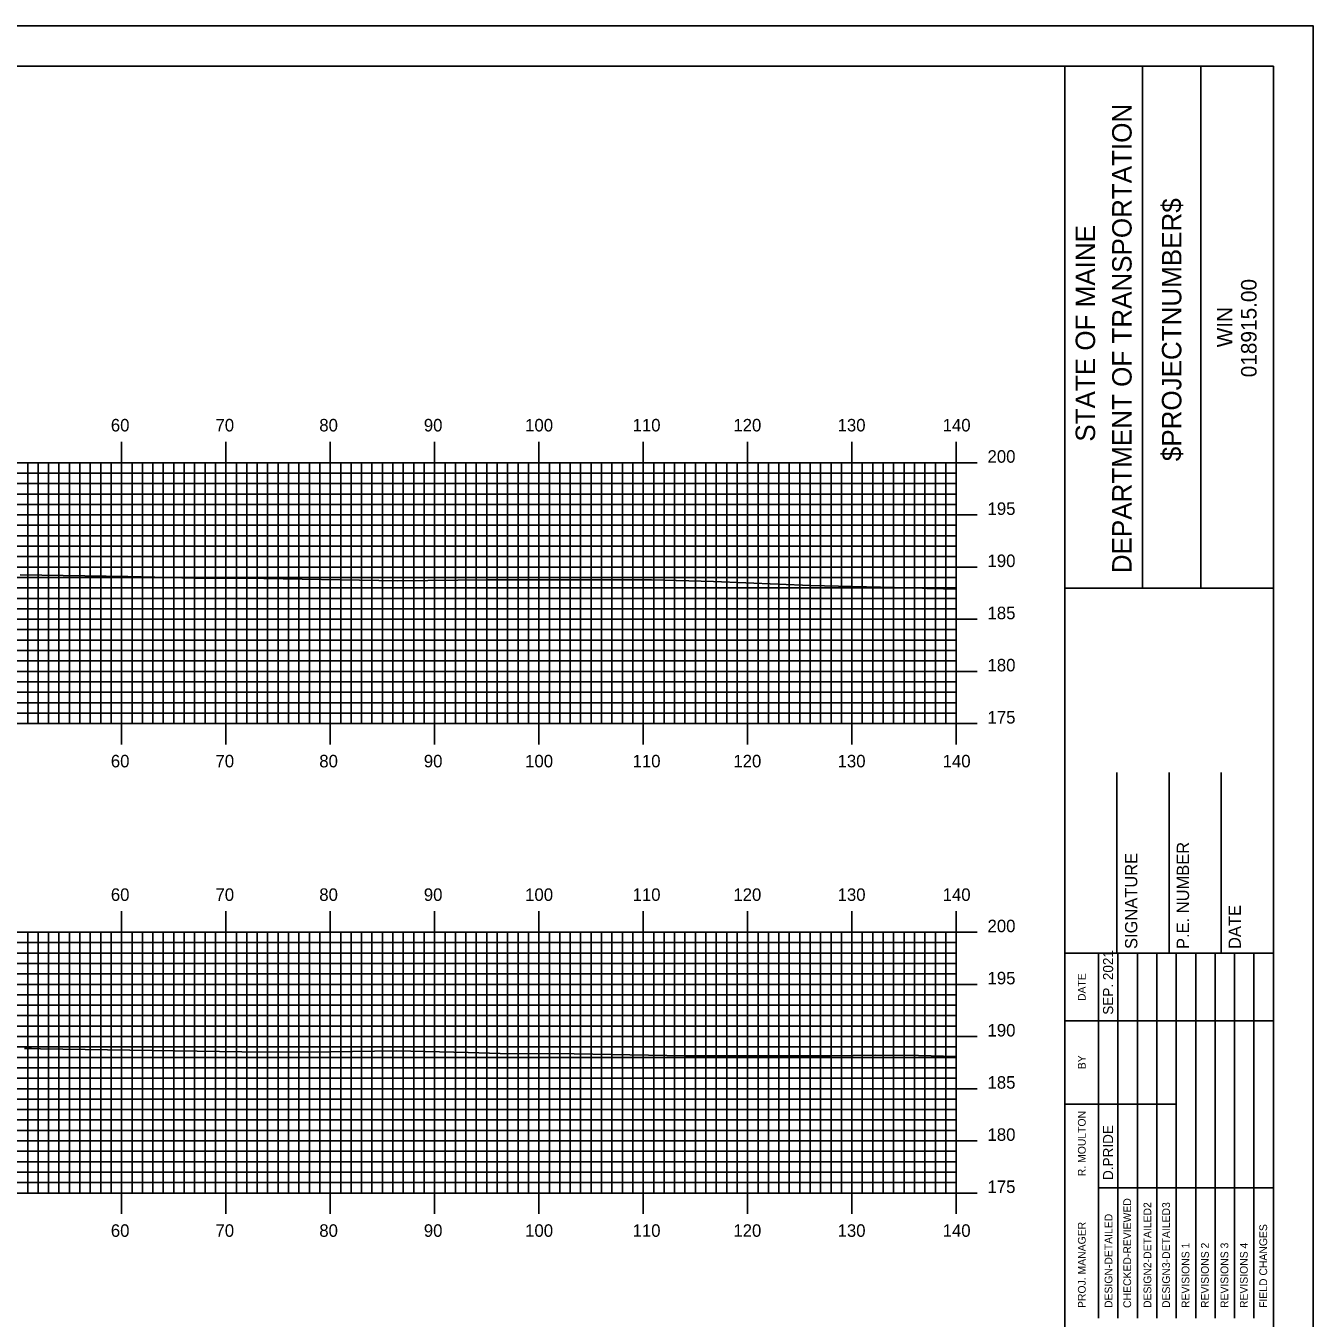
# Model space of a CAD drawing. Extents: x 1797994 to 1798337, y 442591 to 442811.
# Drawn here: x 1798210.8 to 1798334.2, y 442686.7 to 442810.5 of the extents above; entities that cross this region are included whole.
import ezdxf

# ---------------------------------------------------------------- set-up
doc = ezdxf.new("R2010")
doc.units = 0
for name, color, linetype in [('BORDER', 7, 'Continuous'), ('H_V ANNOTATION', 7, 'Continuous'), ('MAJOR', 7, 'Continuous'), ('MINOR', 7, 'Continuous'), ('PLOT BOUNDARY', 7, 'Continuous'), ('S_Roadway_Centerline', 7, 'Continuous')]:
    doc.layers.add(name, color=color, linetype=linetype)

msp = doc.modelspace()

# ---------------------------------------------------------------- linework, layer by layer
at = {"layer": 'BORDER'}
for p, q in [((1798310.36, 442596.67), (1798310.36, 442806.67)), ((1798317.81, 442756.66), (1798317.81, 442806.66)), ((1798323.4, 442756.66), (1798323.4, 442806.66)), ((1798310.36, 442756.65), (1798330.36, 442756.65)), ((1798315.36, 442721.67), (1798315.36, 442738.97)), ((1798320.36, 442721.67), (1798320.36, 442738.97)), ((1798325.36, 442721.67), (1798325.36, 442738.97)), ((1798310.36, 442721.67), (1798330.36, 442721.67))]:
    msp.add_line(p, q, dxfattribs=at)
msp.add_lwpolyline([(1798010.36, 442596.67), (1798330.36, 442596.67), (1798330.36, 442806.67), (1798010.36, 442806.67)], close=True, dxfattribs=at)
for points in [[(1798313.59, 442715.17), (1798313.59, 442721.67)], [(1798315.45, 442686.68), (1798315.45, 442721.67)], [(1798317.32, 442721.67), (1798317.32, 442686.68)], [(1798319.18, 442686.68), (1798319.18, 442721.67)], [(1798321.04, 442686.68), (1798321.04, 442721.67)], [(1798322.91, 442686.68), (1798322.91, 442721.67)], [(1798324.77, 442686.68), (1798324.77, 442721.67)], [(1798326.63, 442686.68), (1798326.63, 442721.67)], [(1798328.5, 442686.68), (1798328.5, 442721.67)], [(1798313.59, 442686.68), (1798313.59, 442720.26)], [(1798310.36, 442715.17), (1798330.36, 442715.17)], [(1798310.36, 442707.17), (1798313.59, 442707.17)], [(1798313.59, 442707.17), (1798321.04, 442707.17)], [(1798313.59, 442699.17), (1798330.36, 442699.17)]]:
    msp.add_lwpolyline(points, dxfattribs=at)
at = {"layer": 'MAJOR'}
for p, q in [((1798219.96, 442770.67), (1798219.96, 442768.67)), ((1798229.96, 442770.67), (1798229.96, 442768.67)), ((1798239.96, 442770.67), (1798239.96, 442768.67)), ((1798249.96, 442770.67), (1798249.96, 442768.67)), ((1798259.96, 442770.67), (1798259.96, 442768.67)), ((1798269.96, 442770.67), (1798269.96, 442768.67)), ((1798279.96, 442770.67), (1798279.96, 442768.67)), ((1798289.96, 442770.67), (1798289.96, 442768.67)), ((1798299.96, 442770.67), (1798299.96, 442768.67)), ((1798019.96, 442768.67), (1798299.96, 442768.67)), ((1798019.96, 442768.67), (1798299.96, 442768.67)), ((1798219.96, 442743.67), (1798219.96, 442768.67)), ((1798229.96, 442743.67), (1798229.96, 442768.67)), ((1798239.96, 442743.67), (1798239.96, 442768.67)), ((1798249.96, 442743.67), (1798249.96, 442768.67)), ((1798259.96, 442743.67), (1798259.96, 442768.67)), ((1798269.96, 442743.67), (1798269.96, 442768.67)), ((1798279.96, 442743.67), (1798279.96, 442768.67)), ((1798289.96, 442743.67), (1798289.96, 442768.67)), ((1798301.96, 442768.67), (1798297.95, 442768.67)), ((1798299.96, 442743.67), (1798299.96, 442768.67)), ((1798299.96, 442743.67), (1798299.96, 442768.67)), ((1798019.96, 442763.67), (1798299.96, 442763.67)), ((1798301.96, 442763.67), (1798297.95, 442763.67)), ((1798019.96, 442758.67), (1798299.96, 442758.67)), ((1798301.96, 442758.67), (1798297.95, 442758.67)), ((1798019.96, 442753.67), (1798299.96, 442753.67)), ((1798301.96, 442753.67), (1798297.95, 442753.67)), ((1798019.96, 442748.67), (1798299.96, 442748.67)), ((1798301.96, 442748.67), (1798297.95, 442748.67)), ((1798019.96, 442743.67), (1798299.96, 442743.67)), ((1798019.96, 442743.67), (1798299.96, 442743.67)), ((1798219.96, 442741.66), (1798219.96, 442743.67)), ((1798229.96, 442741.66), (1798229.96, 442743.67)), ((1798239.96, 442741.66), (1798239.96, 442743.67)), ((1798249.96, 442741.66), (1798249.96, 442743.67)), ((1798259.96, 442741.66), (1798259.96, 442743.67)), ((1798269.96, 442741.66), (1798269.96, 442743.67)), ((1798279.96, 442741.66), (1798279.96, 442743.67)), ((1798289.96, 442741.66), (1798289.96, 442743.67)), ((1798301.96, 442743.67), (1798297.95, 442743.67)), ((1798299.96, 442741.66), (1798299.96, 442743.67)), ((1798219.96, 442725.67), (1798219.96, 442723.67)), ((1798229.96, 442725.67), (1798229.96, 442723.67)), ((1798239.96, 442725.67), (1798239.96, 442723.67)), ((1798249.96, 442725.67), (1798249.96, 442723.67)), ((1798259.96, 442725.67), (1798259.96, 442723.67)), ((1798269.96, 442725.67), (1798269.96, 442723.67)), ((1798279.96, 442725.67), (1798279.96, 442723.67)), ((1798289.96, 442725.67), (1798289.96, 442723.67)), ((1798299.96, 442725.67), (1798299.96, 442723.67)), ((1798019.96, 442723.67), (1798299.96, 442723.67)), ((1798019.96, 442723.67), (1798299.96, 442723.67)), ((1798219.96, 442698.67), (1798219.96, 442723.67)), ((1798229.96, 442698.67), (1798229.96, 442723.67)), ((1798239.96, 442698.67), (1798239.96, 442723.67)), ((1798249.96, 442698.67), (1798249.96, 442723.67)), ((1798259.96, 442698.67), (1798259.96, 442723.67)), ((1798269.96, 442698.67), (1798269.96, 442723.67)), ((1798279.96, 442698.67), (1798279.96, 442723.67)), ((1798289.96, 442698.67), (1798289.96, 442723.67)), ((1798301.96, 442723.67), (1798297.95, 442723.67)), ((1798299.96, 442698.67), (1798299.96, 442723.67)), ((1798299.96, 442698.67), (1798299.96, 442723.67)), ((1798019.96, 442718.67), (1798299.96, 442718.67)), ((1798301.96, 442718.67), (1798297.95, 442718.67)), ((1798019.96, 442713.67), (1798299.96, 442713.67)), ((1798301.96, 442713.67), (1798297.95, 442713.67)), ((1798019.96, 442708.67), (1798299.96, 442708.67)), ((1798301.96, 442708.67), (1798297.95, 442708.67)), ((1798019.96, 442703.67), (1798299.96, 442703.67)), ((1798301.96, 442703.67), (1798297.95, 442703.67)), ((1798019.96, 442698.67), (1798299.96, 442698.67)), ((1798019.96, 442698.67), (1798299.96, 442698.67)), ((1798219.96, 442696.66), (1798219.96, 442698.67)), ((1798229.96, 442696.66), (1798229.96, 442698.67)), ((1798239.96, 442696.66), (1798239.96, 442698.67)), ((1798249.96, 442696.66), (1798249.96, 442698.67)), ((1798259.96, 442696.66), (1798259.96, 442698.67)), ((1798269.96, 442696.66), (1798269.96, 442698.67)), ((1798279.96, 442696.66), (1798279.96, 442698.67)), ((1798289.96, 442696.66), (1798289.96, 442698.67)), ((1798301.96, 442698.67), (1798297.95, 442698.67)), ((1798299.96, 442696.66), (1798299.96, 442698.67))]:
    msp.add_line(p, q, dxfattribs=at)
at = {"layer": 'MINOR'}
for p, q in [((1798210.96, 442743.67), (1798210.96, 442768.67)), ((1798211.96, 442743.67), (1798211.96, 442768.67)), ((1798212.96, 442743.67), (1798212.96, 442768.67)), ((1798213.96, 442743.67), (1798213.96, 442768.67)), ((1798214.96, 442743.67), (1798214.96, 442768.67)), ((1798215.96, 442743.67), (1798215.96, 442768.67)), ((1798216.96, 442743.67), (1798216.96, 442768.67)), ((1798217.96, 442743.67), (1798217.96, 442768.67)), ((1798218.96, 442743.67), (1798218.96, 442768.67)), ((1798220.96, 442743.67), (1798220.96, 442768.67)), ((1798221.96, 442743.67), (1798221.96, 442768.67)), ((1798222.96, 442743.67), (1798222.96, 442768.67)), ((1798223.96, 442743.67), (1798223.96, 442768.67)), ((1798224.96, 442743.67), (1798224.96, 442768.67)), ((1798225.96, 442743.67), (1798225.96, 442768.67)), ((1798226.96, 442743.67), (1798226.96, 442768.67)), ((1798227.96, 442743.67), (1798227.96, 442768.67)), ((1798228.96, 442743.67), (1798228.96, 442768.67)), ((1798230.96, 442743.67), (1798230.96, 442768.67)), ((1798231.96, 442743.67), (1798231.96, 442768.67)), ((1798232.96, 442743.67), (1798232.96, 442768.67)), ((1798233.96, 442743.67), (1798233.96, 442768.67)), ((1798234.96, 442743.67), (1798234.96, 442768.67)), ((1798235.96, 442743.67), (1798235.96, 442768.67)), ((1798236.96, 442743.67), (1798236.96, 442768.67)), ((1798237.96, 442743.67), (1798237.96, 442768.67)), ((1798238.96, 442743.67), (1798238.96, 442768.67)), ((1798240.96, 442743.67), (1798240.96, 442768.67)), ((1798241.96, 442743.67), (1798241.96, 442768.67)), ((1798242.96, 442743.67), (1798242.96, 442768.67)), ((1798243.96, 442743.67), (1798243.96, 442768.67)), ((1798244.96, 442743.67), (1798244.96, 442768.67)), ((1798245.96, 442743.67), (1798245.96, 442768.67)), ((1798246.96, 442743.67), (1798246.96, 442768.67)), ((1798247.96, 442743.67), (1798247.96, 442768.67)), ((1798248.96, 442743.67), (1798248.96, 442768.67)), ((1798250.96, 442743.67), (1798250.96, 442768.67)), ((1798251.96, 442743.67), (1798251.96, 442768.67)), ((1798252.96, 442743.67), (1798252.96, 442768.67)), ((1798253.96, 442743.67), (1798253.96, 442768.67)), ((1798254.96, 442743.67), (1798254.96, 442768.67)), ((1798255.96, 442743.67), (1798255.96, 442768.67)), ((1798256.96, 442743.67), (1798256.96, 442768.67)), ((1798257.96, 442743.67), (1798257.96, 442768.67)), ((1798258.96, 442743.67), (1798258.96, 442768.67)), ((1798260.96, 442743.67), (1798260.96, 442768.67)), ((1798261.96, 442743.67), (1798261.96, 442768.67)), ((1798262.96, 442743.67), (1798262.96, 442768.67)), ((1798263.96, 442743.67), (1798263.96, 442768.67)), ((1798264.96, 442743.67), (1798264.96, 442768.67)), ((1798265.96, 442743.67), (1798265.96, 442768.67)), ((1798266.96, 442743.67), (1798266.96, 442768.67)), ((1798267.96, 442743.67), (1798267.96, 442768.67)), ((1798268.96, 442743.67), (1798268.96, 442768.67)), ((1798270.96, 442743.67), (1798270.96, 442768.67)), ((1798271.96, 442743.67), (1798271.96, 442768.67)), ((1798272.96, 442743.67), (1798272.96, 442768.67)), ((1798273.96, 442743.67), (1798273.96, 442768.67)), ((1798274.96, 442743.67), (1798274.96, 442768.67)), ((1798275.96, 442743.67), (1798275.96, 442768.67)), ((1798276.96, 442743.67), (1798276.96, 442768.67)), ((1798277.96, 442743.67), (1798277.96, 442768.67)), ((1798278.96, 442743.67), (1798278.96, 442768.67)), ((1798280.96, 442743.67), (1798280.96, 442768.67)), ((1798281.96, 442743.67), (1798281.96, 442768.67)), ((1798282.96, 442743.67), (1798282.96, 442768.67)), ((1798283.96, 442743.67), (1798283.96, 442768.67)), ((1798284.96, 442743.67), (1798284.96, 442768.67)), ((1798285.96, 442743.67), (1798285.96, 442768.67)), ((1798286.96, 442743.67), (1798286.96, 442768.67)), ((1798287.96, 442743.67), (1798287.96, 442768.67)), ((1798288.96, 442743.67), (1798288.96, 442768.67)), ((1798290.96, 442743.67), (1798290.96, 442768.67)), ((1798291.96, 442743.67), (1798291.96, 442768.67)), ((1798292.96, 442743.67), (1798292.96, 442768.67)), ((1798293.96, 442743.67), (1798293.96, 442768.67)), ((1798294.96, 442743.67), (1798294.96, 442768.67)), ((1798295.96, 442743.67), (1798295.96, 442768.67)), ((1798296.96, 442743.67), (1798296.96, 442768.67)), ((1798297.96, 442743.67), (1798297.96, 442768.67)), ((1798298.96, 442743.67), (1798298.96, 442768.67)), ((1798019.96, 442767.67), (1798299.96, 442767.67)), ((1798299.96, 442767.67), (1798297.95, 442767.67)), ((1798019.96, 442766.67), (1798299.96, 442766.67)), ((1798299.96, 442766.67), (1798297.95, 442766.67)), ((1798019.96, 442765.67), (1798299.96, 442765.67)), ((1798299.96, 442765.67), (1798297.95, 442765.67)), ((1798019.96, 442764.67), (1798299.96, 442764.67)), ((1798299.96, 442764.67), (1798297.95, 442764.67)), ((1798019.96, 442762.67), (1798299.96, 442762.67)), ((1798299.96, 442762.67), (1798297.95, 442762.67)), ((1798019.96, 442761.67), (1798299.96, 442761.67)), ((1798299.96, 442761.67), (1798297.95, 442761.67)), ((1798019.96, 442760.67), (1798299.96, 442760.67)), ((1798299.96, 442760.67), (1798297.95, 442760.67)), ((1798019.96, 442759.67), (1798299.96, 442759.67)), ((1798299.96, 442759.67), (1798297.95, 442759.67)), ((1798019.96, 442757.67), (1798299.96, 442757.67)), ((1798299.96, 442757.67), (1798297.95, 442757.67)), ((1798019.96, 442756.67), (1798299.96, 442756.67)), ((1798299.96, 442756.67), (1798297.95, 442756.67)), ((1798019.96, 442755.67), (1798299.96, 442755.67)), ((1798299.96, 442755.67), (1798297.95, 442755.67)), ((1798019.96, 442754.67), (1798299.96, 442754.67)), ((1798299.96, 442754.67), (1798297.95, 442754.67)), ((1798019.96, 442752.67), (1798299.96, 442752.67)), ((1798299.96, 442752.67), (1798297.95, 442752.67)), ((1798019.96, 442751.67), (1798299.96, 442751.67)), ((1798299.96, 442751.67), (1798297.95, 442751.67)), ((1798019.96, 442750.67), (1798299.96, 442750.67)), ((1798299.96, 442750.67), (1798297.95, 442750.67)), ((1798019.96, 442749.67), (1798299.96, 442749.67)), ((1798299.96, 442749.67), (1798297.95, 442749.67)), ((1798019.96, 442747.67), (1798299.96, 442747.67)), ((1798299.96, 442747.67), (1798297.95, 442747.67)), ((1798019.96, 442746.67), (1798299.96, 442746.67)), ((1798299.96, 442746.67), (1798297.95, 442746.67)), ((1798019.96, 442745.67), (1798299.96, 442745.67)), ((1798299.96, 442745.67), (1798297.95, 442745.67)), ((1798019.96, 442744.67), (1798299.96, 442744.67)), ((1798299.96, 442744.67), (1798297.95, 442744.67)), ((1798210.96, 442698.67), (1798210.96, 442723.67)), ((1798211.96, 442698.67), (1798211.96, 442723.67)), ((1798212.96, 442698.67), (1798212.96, 442723.67)), ((1798213.96, 442698.67), (1798213.96, 442723.67)), ((1798214.96, 442698.67), (1798214.96, 442723.67)), ((1798215.96, 442698.67), (1798215.96, 442723.67)), ((1798216.96, 442698.67), (1798216.96, 442723.67)), ((1798217.96, 442698.67), (1798217.96, 442723.67)), ((1798218.96, 442698.67), (1798218.96, 442723.67)), ((1798220.96, 442698.67), (1798220.96, 442723.67)), ((1798221.96, 442698.67), (1798221.96, 442723.67)), ((1798222.96, 442698.67), (1798222.96, 442723.67)), ((1798223.96, 442698.67), (1798223.96, 442723.67)), ((1798224.96, 442698.67), (1798224.96, 442723.67)), ((1798225.96, 442698.67), (1798225.96, 442723.67)), ((1798226.96, 442698.67), (1798226.96, 442723.67)), ((1798227.96, 442698.67), (1798227.96, 442723.67)), ((1798228.96, 442698.67), (1798228.96, 442723.67)), ((1798230.96, 442698.67), (1798230.96, 442723.67)), ((1798231.96, 442698.67), (1798231.96, 442723.67)), ((1798232.96, 442698.67), (1798232.96, 442723.67)), ((1798233.96, 442698.67), (1798233.96, 442723.67)), ((1798234.96, 442698.67), (1798234.96, 442723.67)), ((1798235.96, 442698.67), (1798235.96, 442723.67)), ((1798236.96, 442698.67), (1798236.96, 442723.67)), ((1798237.96, 442698.67), (1798237.96, 442723.67)), ((1798238.96, 442698.67), (1798238.96, 442723.67)), ((1798240.96, 442698.67), (1798240.96, 442723.67)), ((1798241.96, 442698.67), (1798241.96, 442723.67)), ((1798242.96, 442698.67), (1798242.96, 442723.67)), ((1798243.96, 442698.67), (1798243.96, 442723.67)), ((1798244.96, 442698.67), (1798244.96, 442723.67)), ((1798245.96, 442698.67), (1798245.96, 442723.67)), ((1798246.96, 442698.67), (1798246.96, 442723.67)), ((1798247.96, 442698.67), (1798247.96, 442723.67)), ((1798248.96, 442698.67), (1798248.96, 442723.67)), ((1798250.96, 442698.67), (1798250.96, 442723.67)), ((1798251.96, 442698.67), (1798251.96, 442723.67)), ((1798252.96, 442698.67), (1798252.96, 442723.67)), ((1798253.96, 442698.67), (1798253.96, 442723.67)), ((1798254.96, 442698.67), (1798254.96, 442723.67)), ((1798255.96, 442698.67), (1798255.96, 442723.67)), ((1798256.96, 442698.67), (1798256.96, 442723.67)), ((1798257.96, 442698.67), (1798257.96, 442723.67)), ((1798258.96, 442698.67), (1798258.96, 442723.67)), ((1798260.96, 442698.67), (1798260.96, 442723.67)), ((1798261.96, 442698.67), (1798261.96, 442723.67)), ((1798262.96, 442698.67), (1798262.96, 442723.67)), ((1798263.96, 442698.67), (1798263.96, 442723.67)), ((1798264.96, 442698.67), (1798264.96, 442723.67)), ((1798265.96, 442698.67), (1798265.96, 442723.67)), ((1798266.96, 442698.67), (1798266.96, 442723.67)), ((1798267.96, 442698.67), (1798267.96, 442723.67)), ((1798268.96, 442698.67), (1798268.96, 442723.67)), ((1798270.96, 442698.67), (1798270.96, 442723.67)), ((1798271.96, 442698.67), (1798271.96, 442723.67)), ((1798272.96, 442698.67), (1798272.96, 442723.67)), ((1798273.96, 442698.67), (1798273.96, 442723.67)), ((1798274.96, 442698.67), (1798274.96, 442723.67)), ((1798275.96, 442698.67), (1798275.96, 442723.67)), ((1798276.96, 442698.67), (1798276.96, 442723.67)), ((1798277.96, 442698.67), (1798277.96, 442723.67)), ((1798278.96, 442698.67), (1798278.96, 442723.67)), ((1798280.96, 442698.67), (1798280.96, 442723.67)), ((1798281.96, 442698.67), (1798281.96, 442723.67)), ((1798282.96, 442698.67), (1798282.96, 442723.67)), ((1798283.96, 442698.67), (1798283.96, 442723.67)), ((1798284.96, 442698.67), (1798284.96, 442723.67)), ((1798285.96, 442698.67), (1798285.96, 442723.67)), ((1798286.96, 442698.67), (1798286.96, 442723.67)), ((1798287.96, 442698.67), (1798287.96, 442723.67)), ((1798288.96, 442698.67), (1798288.96, 442723.67)), ((1798290.96, 442698.67), (1798290.96, 442723.67)), ((1798291.96, 442698.67), (1798291.96, 442723.67)), ((1798292.96, 442698.67), (1798292.96, 442723.67)), ((1798293.96, 442698.67), (1798293.96, 442723.67)), ((1798294.96, 442698.67), (1798294.96, 442723.67)), ((1798295.96, 442698.67), (1798295.96, 442723.67)), ((1798296.96, 442698.67), (1798296.96, 442723.67)), ((1798297.96, 442698.67), (1798297.96, 442723.67)), ((1798298.96, 442698.67), (1798298.96, 442723.67)), ((1798019.96, 442722.67), (1798299.96, 442722.67)), ((1798019.96, 442721.67), (1798299.96, 442721.67)), ((1798299.96, 442722.67), (1798297.95, 442722.67)), ((1798299.96, 442721.67), (1798297.95, 442721.67)), ((1798019.96, 442720.67), (1798299.96, 442720.67)), ((1798299.96, 442720.67), (1798297.95, 442720.67)), ((1798019.96, 442719.67), (1798299.96, 442719.67)), ((1798299.96, 442719.67), (1798297.95, 442719.67)), ((1798019.96, 442717.67), (1798299.96, 442717.67)), ((1798019.96, 442716.67), (1798299.96, 442716.67)), ((1798299.96, 442717.67), (1798297.95, 442717.67)), ((1798299.96, 442716.67), (1798297.95, 442716.67)), ((1798019.96, 442715.67), (1798299.96, 442715.67)), ((1798299.96, 442715.67), (1798297.95, 442715.67)), ((1798019.96, 442714.67), (1798299.96, 442714.67)), ((1798299.96, 442714.67), (1798297.95, 442714.67)), ((1798019.96, 442712.67), (1798299.96, 442712.67)), ((1798019.96, 442711.67), (1798299.96, 442711.67)), ((1798299.96, 442712.67), (1798297.95, 442712.67)), ((1798299.96, 442711.67), (1798297.95, 442711.67)), ((1798019.96, 442710.67), (1798299.96, 442710.67)), ((1798299.96, 442710.67), (1798297.95, 442710.67)), ((1798019.96, 442709.67), (1798299.96, 442709.67)), ((1798299.96, 442709.67), (1798297.95, 442709.67)), ((1798019.96, 442707.67), (1798299.96, 442707.67)), ((1798019.96, 442706.67), (1798299.96, 442706.67)), ((1798299.96, 442707.67), (1798297.95, 442707.67)), ((1798299.96, 442706.67), (1798297.95, 442706.67)), ((1798019.96, 442705.67), (1798299.96, 442705.67)), ((1798299.96, 442705.67), (1798297.95, 442705.67)), ((1798019.96, 442704.67), (1798299.96, 442704.67)), ((1798299.96, 442704.67), (1798297.95, 442704.67)), ((1798019.96, 442702.67), (1798299.96, 442702.67)), ((1798019.96, 442701.67), (1798299.96, 442701.67)), ((1798299.96, 442702.67), (1798297.95, 442702.67)), ((1798299.96, 442701.67), (1798297.95, 442701.67)), ((1798019.96, 442700.67), (1798299.96, 442700.67)), ((1798299.96, 442700.67), (1798297.95, 442700.67)), ((1798019.96, 442699.67), (1798299.96, 442699.67)), ((1798299.96, 442699.67), (1798297.95, 442699.67))]:
    msp.add_line(p, q, dxfattribs=at)
at = {"layer": 'PLOT BOUNDARY'}
msp.add_lwpolyline([(1797994.17, 442590.55), (1798334.17, 442590.55), (1798334.17, 442810.55), (1797994.17, 442810.55)], close=True, dxfattribs=at)
at = {"layer": 'S_Roadway_Centerline'}
for points in [[(1798210.23, 442757.91), (1798220.57, 442757.78), (1798227.02, 442757.6), (1798231.76, 442757.6), (1798246.44, 442757.34), (1798255.06, 442757.43), (1798270.74, 442757.44), (1798276.71, 442757.28), (1798285.99, 442756.89), (1798296.74, 442756.64), (1798297.14, 442756.62), (1798297.48, 442756.62), (1798299.96, 442756.55)], [(1798210.64, 442712.52), (1798211.32, 442712.52), (1798212.18, 442712.5), (1798231.5, 442712.19), (1798237.89, 442712.18), (1798246.32, 442712.29), (1798253.19, 442712.13), (1798256.24, 442712.05), (1798263.34, 442712.02), (1798274, 442711.82), (1798287.98, 442711.81), (1798292.18, 442711.87), (1798296.35, 442711.86), (1798299.96, 442711.75)]]:
    msp.add_lwpolyline(points, dxfattribs=at)

# ---------------------------------------------------------------- texts
at = {"layer": 'BORDER'}
for s, height, p in [('DEPARTMENT OF TRANSPORTATION', 1.8635, (1798316.77, 442758.08)), ('$PROJECTNUMBER$', 1.8635, (1798321.54, 442768.82)), ('STATE OF MAINE', 1.8635, (1798313.27, 442770.69)), ('018915.00', 1.491, (1798328.75, 442776.86)), ('WIN', 1.491, (1798326.43, 442779.73)), ('P.E. NUMBER', 1.1811, (1798322.28, 442722.06)), ('SIGNATURE', 1.181, (1798317.32, 442722.06)), ('DATE', 1.181, (1798327.24, 442722.06)), ('SEP. 2021', 0.969, (1798315, 442715.76)), ('DATE', 0.743, (1798312.37, 442717.08)), ('BY', 0.743, (1798312.37, 442710.54)), ('R. MOULTON', 0.745, (1798312.37, 442700.28)), ('D.PRIDE', 0.969, (1798315, 442699.92)), ('CHECKED-REVIEWED', 0.7455, (1798316.72, 442687.65)), ('DESIGN2-DETAILED2', 0.7455, (1798318.66, 442687.65)), ('DESIGN3-DETAILED3', 0.7455, (1798320.45, 442687.65)), ('PROJ. MANAGER', 0.7455, (1798312.37, 442687.65)), ('DESIGN-DETAILED', 0.7455, (1798314.93, 442687.65)), ('FIELD CHANGES', 0.7455, (1798329.76, 442687.65)), ('REVISIONS 1', 0.7455, (1798322.31, 442687.65)), ('REVISIONS 2', 0.7455, (1798324.17, 442687.65)), ('REVISIONS 3', 0.7455, (1798326.04, 442687.65)), ('REVISIONS 4', 0.7455, (1798327.9, 442687.65))]:
    msp.add_text(s, height=height, rotation=90, dxfattribs=at).set_placement(p)
at = {"layer": 'H_V ANNOTATION'}
for s, p in [('60', (1798218.93, 442771.67)), ('70', (1798228.96, 442771.67)), ('80', (1798238.91, 442771.67)), ('90', (1798248.93, 442771.67)), ('100', (1798258.64, 442771.67)), ('110', (1798268.94, 442771.67)), ('120', (1798278.6, 442771.67)), ('130', (1798288.59, 442771.67)), ('140', (1798298.66, 442771.67)), ('200', (1798302.96, 442768.67)), ('195', (1798302.96, 442763.67)), ('190', (1798302.96, 442758.67)), ('185', (1798302.96, 442753.67)), ('180', (1798302.96, 442748.67)), ('175', (1798302.96, 442743.67)), ('60', (1798218.93, 442739.47)), ('70', (1798228.96, 442739.47)), ('80', (1798238.91, 442739.47)), ('90', (1798248.93, 442739.47)), ('100', (1798258.64, 442739.47)), ('110', (1798268.94, 442739.47)), ('120', (1798278.6, 442739.47)), ('130', (1798288.59, 442739.47)), ('140', (1798298.66, 442739.47)), ('60', (1798218.93, 442726.67)), ('70', (1798228.96, 442726.67)), ('80', (1798238.91, 442726.67)), ('90', (1798248.93, 442726.67)), ('100', (1798258.64, 442726.67)), ('110', (1798268.94, 442726.67)), ('120', (1798278.6, 442726.67)), ('130', (1798288.59, 442726.67)), ('140', (1798298.66, 442726.67)), ('200', (1798302.96, 442723.67)), ('195', (1798302.96, 442718.67)), ('190', (1798302.96, 442713.67)), ('185', (1798302.96, 442708.67)), ('180', (1798302.96, 442703.67)), ('175', (1798302.96, 442698.67)), ('60', (1798218.93, 442694.47)), ('70', (1798228.96, 442694.47)), ('80', (1798238.91, 442694.47)), ('90', (1798248.93, 442694.47)), ('100', (1798258.64, 442694.47)), ('110', (1798268.94, 442694.47)), ('120', (1798278.6, 442694.47)), ('130', (1798288.59, 442694.47)), ('140', (1798298.66, 442694.47))]:
    msp.add_text(s, height=1.2, dxfattribs=at).set_placement(p)

doc.saveas('drawing.dxf')
